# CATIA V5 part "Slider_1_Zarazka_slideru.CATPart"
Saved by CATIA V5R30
Part number: Slider_1_Zarazka_slideru
Publications: "DrillHole_CapScrew_E1200_1.1_"
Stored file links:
  E:\Bakalarka\Model\Forma_v7\Slider_1_Zarazka_slideru.CATPart
  E:\Bakalarka\Model\Forma_v7\Forma.CATProduct
  E:\Bakalarka\Model\Forma_v7\TlgItf_Zarazka_slideru.CATProduct

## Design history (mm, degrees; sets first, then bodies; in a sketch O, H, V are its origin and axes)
Body1 (main body)
Body2 "DrillHole"
  Solid1: linked copy from another document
